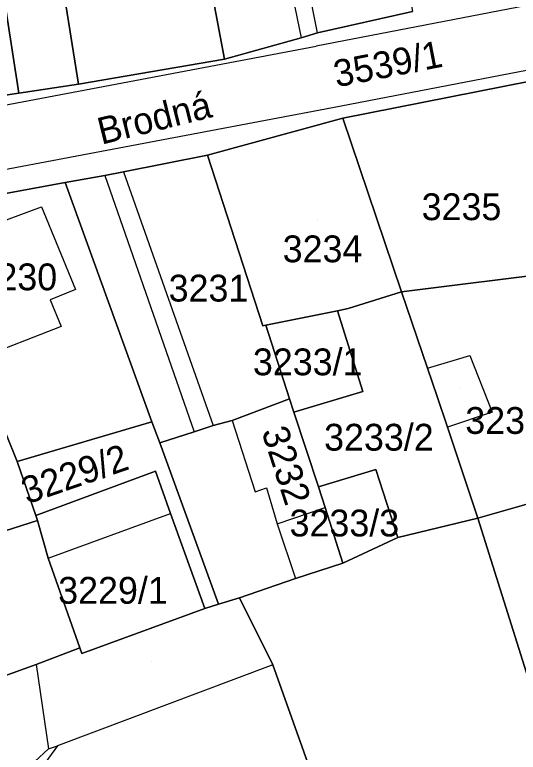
# Model space of a CAD drawing. Extents: x -262657 to -261595, y -1238015 to -1237156.
# Drawn here: x -261893.4 to -261855.8, y -1237748.7 to -1237693.7 of the extents above; entities that cross this region are included whole.
import ezdxf

# ---------------------------------------------------------------- set-up
doc = ezdxf.new("R2010")
doc.units = 0
for name, color, linetype in [('body_kn', 7, 'Continuous'), ('kladpar_druhypozemkov', 7, 'Continuous'), ('kladpar_hranice', 7, 'Continuous'), ('kladpar_parcelnecisla', 7, 'Continuous'), ('kladpar_plochy', 7, 'Continuous'), ('popisy', 7, 'Continuous'), ('zappar_hrandruhpozemk', 7, 'Continuous')]:
    doc.layers.add(name, color=color, linetype=linetype)

msp = doc.modelspace()

# ---------------------------------------------------------------- linework, layer by layer
at = {"layer": 'body_kn'}
for p, q in [((-261872.02, -1237695.41), (-261872.02, -1237695.41)), ((-261870.79, -1237695.02), (-261870.79, -1237695.02)), ((-261870.79, -1237695.02), (-261870.79, -1237695.02)), ((-261870.9, -1237696.02), (-261870.9, -1237696.02)), ((-261877.74, -1237697), (-261877.74, -1237697)), ((-261877.74, -1237697), (-261877.74, -1237697)), ((-261888.62, -1237698.85), (-261888.62, -1237698.85)), ((-261888.62, -1237698.85), (-261888.62, -1237698.85)), ((-261893.08, -1237699.52), (-261893.08, -1237699.52)), ((-261869.66, -1237700.6), (-261869.66, -1237700.6)), ((-261869.66, -1237700.6), (-261869.66, -1237700.6)), ((-261868.9, -1237701.4), (-261868.9, -1237701.4)), ((-261868.9, -1237701.4), (-261868.9, -1237701.4)), ((-261879, -1237704.16), (-261879, -1237704.16)), ((-261879, -1237704.16), (-261879, -1237704.16)), ((-261885.26, -1237705.39), (-261885.26, -1237705.39)), ((-261885.26, -1237705.39), (-261885.26, -1237705.39)), ((-261886.66, -1237705.67), (-261886.66, -1237705.67)), ((-261886.66, -1237705.67), (-261886.66, -1237705.67)), ((-261889.62, -1237706.2), (-261889.62, -1237706.2)), ((-261889.62, -1237706.2), (-261889.62, -1237706.2)), ((-261891.39, -1237708.01), (-261891.39, -1237708.01)), ((-261888.86, -1237714.17), (-261888.86, -1237714.17)), ((-261864.53, -1237714.35), (-261864.53, -1237714.35)), ((-261864.53, -1237714.35), (-261864.53, -1237714.35)), ((-261890.75, -1237714.95), (-261890.75, -1237714.95)), ((-261869.3, -1237715.76), (-261869.3, -1237715.76)), ((-261869.3, -1237715.76), (-261869.3, -1237715.76)), ((-261868.51, -1237715.6), (-261868.51, -1237715.6)), ((-261889.93, -1237716.93), (-261889.93, -1237716.93)), ((-261874.88, -1237716.87), (-261874.88, -1237716.87)), ((-261874.65, -1237716.83), (-261874.65, -1237716.83)), ((-261859.43, -1237719.09), (-261859.43, -1237719.09)), ((-261862.57, -1237720.05), (-261862.57, -1237720.05)), ((-261862.57, -1237720.05), (-261862.57, -1237720.05)), ((-261867.41, -1237721.79), (-261867.41, -1237721.79)), ((-261872.88, -1237722.33), (-261872.88, -1237722.33)), ((-261861.86, -1237722.15), (-261861.86, -1237722.15)), ((-261872.55, -1237723.33), (-261872.55, -1237723.33)), ((-261857.76, -1237723.31), (-261857.76, -1237723.31)), ((-261883.15, -1237724.04), (-261883.15, -1237724.04)), ((-261877.16, -1237723.93), (-261877.16, -1237723.93)), ((-261877.16, -1237723.93), (-261877.16, -1237723.93)), ((-261878.57, -1237724.31), (-261878.57, -1237724.31)), ((-261861.09, -1237724.45), (-261861.09, -1237724.45)), ((-261880, -1237724.78), (-261880, -1237724.78)), ((-261882.57, -1237725.61), (-261882.57, -1237725.61)), ((-261882.57, -1237725.61), (-261882.57, -1237725.61)), ((-261893.22, -1237726.99), (-261893.22, -1237726.99)), ((-261893.22, -1237726.99), (-261893.22, -1237726.99)), ((-261882.89, -1237727.73), (-261882.89, -1237727.73)), ((-261866.43, -1237727.59), (-261866.43, -1237727.59)), ((-261866.43, -1237727.59), (-261866.43, -1237727.59)), ((-261874.6, -1237728.96), (-261874.6, -1237728.96)), ((-261870.72, -1237728.89), (-261870.72, -1237728.89)), ((-261875.45, -1237729.25), (-261875.45, -1237729.25)), ((-261870.21, -1237730.44), (-261870.21, -1237730.44)), ((-261891.81, -1237731.03), (-261891.81, -1237731.03)), ((-261881.77, -1237730.88), (-261881.77, -1237730.88)), ((-261858.82, -1237731.22), (-261858.82, -1237731.22)), ((-261858.82, -1237731.22), (-261858.82, -1237731.22)), ((-261891.68, -1237731.41), (-261891.68, -1237731.41)), ((-261891.68, -1237731.41), (-261891.68, -1237731.41)), ((-261873.79, -1237731.64), (-261873.79, -1237731.64)), ((-261864.8, -1237732.66), (-261864.8, -1237732.66)), ((-261890.9, -1237734.21), (-261890.9, -1237734.21)), ((-261890.9, -1237734.21), (-261890.9, -1237734.21)), ((-261868.9, -1237734.59), (-261868.9, -1237734.59)), ((-261872.44, -1237735.73), (-261872.44, -1237735.73)), ((-261876.61, -1237737.16), (-261876.61, -1237737.16)), ((-261878.19, -1237737.65), (-261878.19, -1237737.65)), ((-261879.2, -1237737.96), (-261879.2, -1237737.96)), ((-261888.53, -1237740.9), (-261888.53, -1237740.9)), ((-261888.53, -1237740.9), (-261888.53, -1237740.9)), ((-261888.38, -1237741.32), (-261888.38, -1237741.32)), ((-261891.79, -1237742.14), (-261891.79, -1237742.14)), ((-261891.79, -1237742.14), (-261891.79, -1237742.14)), ((-261874.12, -1237742.17), (-261874.12, -1237742.17)), ((-261874.12, -1237742.17), (-261874.12, -1237742.17)), ((-261890.21, -1237748.21), (-261890.21, -1237748.21)), ((-261890.88, -1237748.42), (-261890.88, -1237748.42))]:
    msp.add_line(p, q, dxfattribs=at)
at = {"layer": 'kladpar_druhypozemkov'}
for p, q in [((-261865.14, -1237696.86), (-261865.14, -1237696.86)), ((-261859.49, -1237706.97), (-261859.49, -1237706.97)), ((-261870.82, -1237709.03), (-261870.82, -1237709.03)), ((-261879.58, -1237712.98), (-261879.58, -1237712.98)), ((-261871.18, -1237718.51), (-261871.18, -1237718.51)), ((-261860.21, -1237721.57), (-261860.21, -1237721.57)), ((-261865.05, -1237724.07), (-261865.05, -1237724.07)), ((-261887.65, -1237727.31), (-261887.65, -1237727.31)), ((-261872.38, -1237727.33), (-261872.38, -1237727.33)), ((-261867.69, -1237730.79), (-261867.69, -1237730.79)), ((-261885.56, -1237735.83), (-261885.56, -1237735.83)), ((-261883.15, -1237741.94), (-261883.15, -1237741.94))]:
    msp.add_line(p, q, dxfattribs=at)
at = {"layer": 'kladpar_hranice'}
for points in [[(-261888.62, -1237698.85), (-261893.08, -1237699.52), (-261894.9, -1237687.92), (-261895.29, -1237685.45), (-261896.29, -1237679.1), (-261888.4, -1237677.17), (-261881.43, -1237675.43), (-261880.83, -1237679.94), (-261880.07, -1237684.56), (-261890.62, -1237686.47), (-261890.23, -1237688.87), (-261888.62, -1237698.85)], [(-261904.39, -1237680.71), (-261900.65, -1237679.95), (-261896.29, -1237679.1), (-261895.29, -1237685.45), (-261894.9, -1237687.92), (-261893.08, -1237699.52), (-261899.25, -1237700.43), (-261900.74, -1237700.72), (-261902.42, -1237690.86), (-261903.46, -1237685.13), (-261904.39, -1237680.71)], [(-261877.74, -1237697), (-261880.07, -1237684.56), (-261874.6, -1237683.14), (-261874.06, -1237685.43), (-261872.78, -1237685.14), (-261865.48, -1237683.57), (-261863.71, -1237693.45), (-261870.79, -1237695.02), (-261872.02, -1237695.41), (-261877.74, -1237697)], [(-261877.74, -1237697), (-261888.62, -1237698.85), (-261890.23, -1237688.87), (-261890.62, -1237686.47), (-261880.07, -1237684.56), (-261877.74, -1237697)], [(-261815.65, -1237691.39), (-261826.22, -1237693.91), (-261829.24, -1237694.55), (-261838.83, -1237696.08), (-261842.59, -1237696.75), (-261854.92, -1237698.64), (-261868.9, -1237701.4), (-261879, -1237704.16), (-261885.26, -1237705.39), (-261886.66, -1237705.67), (-261889.62, -1237706.2), (-261900.57, -1237708.21)], [(-261899.25, -1237700.43), (-261893.08, -1237699.52), (-261888.62, -1237698.85), (-261877.74, -1237697), (-261872.02, -1237695.41), (-261870.79, -1237695.02), (-261863.71, -1237693.45)], [(-261868.9, -1237701.4), (-261854.92, -1237698.64), (-261853.32, -1237708.24), (-261852.56, -1237712.85), (-261864.53, -1237714.35), (-261868.9, -1237701.4)], [(-261879, -1237704.16), (-261868.9, -1237701.4), (-261864.53, -1237714.35), (-261868.51, -1237715.6), (-261869.3, -1237715.76), (-261874.65, -1237716.83), (-261874.88, -1237716.87), (-261879, -1237704.16)], [(-261889.62, -1237706.2), (-261886.66, -1237705.67), (-261885.26, -1237705.39), (-261879, -1237704.16), (-261874.88, -1237716.87), (-261874.65, -1237716.83), (-261872.88, -1237722.33), (-261877.16, -1237723.93), (-261878.57, -1237724.31), (-261880, -1237724.78), (-261882.57, -1237725.61), (-261883.15, -1237724.04), (-261889.62, -1237706.2)], [(-261900.57, -1237708.21), (-261889.62, -1237706.2), (-261883.15, -1237724.04), (-261893.22, -1237726.99), (-261894.88, -1237722.93), (-261896.2, -1237719.38), (-261897.68, -1237715.63), (-261899.41, -1237710.94), (-261900.57, -1237708.21)], [(-261858.82, -1237731.22), (-261861.09, -1237724.45), (-261861.86, -1237722.15), (-261862.57, -1237720.05), (-261864.53, -1237714.35), (-261852.56, -1237712.85), (-261849.93, -1237728.69), (-261858.82, -1237731.22)], [(-261864.53, -1237714.35), (-261862.57, -1237720.05), (-261861.86, -1237722.15), (-261861.09, -1237724.45), (-261858.82, -1237731.22), (-261864.8, -1237732.66), (-261866.43, -1237727.59), (-261870.72, -1237728.89), (-261872.55, -1237723.33), (-261867.41, -1237721.79), (-261869.3, -1237715.76), (-261868.51, -1237715.6), (-261864.53, -1237714.35)], [(-261869.3, -1237715.76), (-261867.41, -1237721.79), (-261872.55, -1237723.33), (-261872.88, -1237722.33), (-261874.65, -1237716.83), (-261869.3, -1237715.76)], [(-261882.57, -1237725.61), (-261880, -1237724.78), (-261878.57, -1237724.31), (-261877.16, -1237723.93), (-261872.88, -1237722.33), (-261872.55, -1237723.33), (-261870.72, -1237728.89), (-261870.21, -1237730.44), (-261868.9, -1237734.59), (-261872.44, -1237735.73), (-261876.61, -1237737.16), (-261878.19, -1237737.65), (-261882.57, -1237725.61)], [(-261894.88, -1237722.93), (-261893.22, -1237726.99), (-261891.81, -1237731.03), (-261891.68, -1237731.41), (-261905.58, -1237735.82), (-261907.23, -1237726.48), (-261894.88, -1237722.93)], [(-261893.22, -1237726.99), (-261883.15, -1237724.04), (-261882.57, -1237725.61), (-261878.19, -1237737.65), (-261879.2, -1237737.96), (-261881.77, -1237730.88), (-261882.89, -1237727.73), (-261891.81, -1237731.03), (-261893.22, -1237726.99)], [(-261891.68, -1237731.41), (-261891.81, -1237731.03), (-261882.89, -1237727.73), (-261881.77, -1237730.88), (-261879.2, -1237737.96), (-261888.38, -1237741.32), (-261888.53, -1237740.9), (-261890.9, -1237734.21), (-261891.68, -1237731.41)], [(-261866.43, -1237727.59), (-261864.8, -1237732.66), (-261868.9, -1237734.59), (-261870.21, -1237730.44), (-261870.72, -1237728.89), (-261866.43, -1237727.59)], [(-261849.93, -1237728.69), (-261845.54, -1237739.43), (-261834.22, -1237737.38), (-261832.97, -1237741.84), (-261853.4, -1237748.46), (-261858.82, -1237731.22), (-261849.93, -1237728.69)], [(-261811.6, -1237755.76), (-261860.68, -1237774.55), (-261869.5, -1237752.69), (-261870.26, -1237752.98), (-261874.12, -1237742.17), (-261876.61, -1237737.16), (-261872.44, -1237735.73), (-261868.9, -1237734.59), (-261864.8, -1237732.66), (-261858.82, -1237731.22), (-261853.4, -1237748.46), (-261848.36, -1237764.27), (-261828.48, -1237757.63), (-261832.97, -1237741.84), (-261834.22, -1237737.38), (-261830.6, -1237736.72), (-261825.65, -1237735.22), (-261815.77, -1237729.89), (-261810.09, -1237729.46)], [(-261888.53, -1237740.9), (-261891.79, -1237742.14), (-261905.24, -1237747), (-261907.41, -1237736.41), (-261905.58, -1237735.82), (-261891.68, -1237731.41), (-261890.9, -1237734.21), (-261888.53, -1237740.9)], [(-261920.12, -1237752.32), (-261918.2, -1237751.63), (-261905.24, -1237747), (-261891.79, -1237742.14), (-261888.53, -1237740.9), (-261888.38, -1237741.32), (-261879.2, -1237737.96), (-261878.19, -1237737.65), (-261876.61, -1237737.16), (-261874.12, -1237742.17), (-261870.26, -1237752.98), (-261885.56, -1237759.1), (-261886.5, -1237759.27), (-261888.28, -1237759.8), (-261893.1, -1237761.58), (-261893.41, -1237761.04), (-261899.15, -1237763.26), (-261908.04, -1237766.48), (-261913.16, -1237768.28), (-261915.03, -1237763.93), (-261915.64, -1237762.81), (-261920.12, -1237752.32)]]:
    msp.add_lwpolyline(points, dxfattribs=at)
at = {"layer": 'kladpar_plochy'}
for points in [[(-261888.62, -1237698.85), (-261893.08, -1237699.52), (-261894.9, -1237687.92), (-261895.29, -1237685.45), (-261896.29, -1237679.1), (-261888.4, -1237677.17), (-261881.43, -1237675.43), (-261880.83, -1237679.94), (-261880.07, -1237684.56), (-261890.62, -1237686.47), (-261890.23, -1237688.87)], [(-261904.39, -1237680.71), (-261900.65, -1237679.95), (-261896.29, -1237679.1), (-261895.29, -1237685.45), (-261894.9, -1237687.92), (-261893.08, -1237699.52), (-261899.25, -1237700.43), (-261900.74, -1237700.72), (-261902.42, -1237690.86), (-261903.46, -1237685.13)], [(-261877.74, -1237697), (-261880.07, -1237684.56), (-261874.6, -1237683.14), (-261874.06, -1237685.43), (-261872.78, -1237685.14), (-261865.48, -1237683.57), (-261863.71, -1237693.45), (-261870.79, -1237695.02), (-261872.02, -1237695.41)], [(-261877.74, -1237697), (-261888.62, -1237698.85), (-261890.23, -1237688.87), (-261890.62, -1237686.47), (-261880.07, -1237684.56)], [(-261868.9, -1237701.4), (-261854.92, -1237698.64), (-261853.32, -1237708.24), (-261852.56, -1237712.85), (-261864.53, -1237714.35)], [(-261879, -1237704.16), (-261868.9, -1237701.4), (-261864.53, -1237714.35), (-261868.51, -1237715.6), (-261869.3, -1237715.76), (-261874.65, -1237716.83), (-261874.88, -1237716.87)], [(-261889.62, -1237706.2), (-261886.66, -1237705.67), (-261885.26, -1237705.39), (-261879, -1237704.16), (-261874.88, -1237716.87), (-261874.65, -1237716.83), (-261872.88, -1237722.33), (-261877.16, -1237723.93), (-261878.57, -1237724.31), (-261880, -1237724.78), (-261882.57, -1237725.61), (-261883.15, -1237724.04)], [(-261900.57, -1237708.21), (-261889.62, -1237706.2), (-261883.15, -1237724.04), (-261893.22, -1237726.99), (-261894.88, -1237722.93), (-261896.2, -1237719.38), (-261897.68, -1237715.63), (-261899.41, -1237710.94)], [(-261858.82, -1237731.22), (-261861.09, -1237724.45), (-261861.86, -1237722.15), (-261862.57, -1237720.05), (-261864.53, -1237714.35), (-261852.56, -1237712.85), (-261849.93, -1237728.69)], [(-261864.53, -1237714.35), (-261862.57, -1237720.05), (-261861.86, -1237722.15), (-261861.09, -1237724.45), (-261858.82, -1237731.22), (-261864.8, -1237732.66), (-261866.43, -1237727.59), (-261870.72, -1237728.89), (-261872.55, -1237723.33), (-261867.41, -1237721.79), (-261869.3, -1237715.76), (-261868.51, -1237715.6)], [(-261869.3, -1237715.76), (-261867.41, -1237721.79), (-261872.55, -1237723.33), (-261872.88, -1237722.33), (-261874.65, -1237716.83)], [(-261882.57, -1237725.61), (-261880, -1237724.78), (-261878.57, -1237724.31), (-261877.16, -1237723.93), (-261872.88, -1237722.33), (-261872.55, -1237723.33), (-261870.72, -1237728.89), (-261870.21, -1237730.44), (-261868.9, -1237734.59), (-261872.44, -1237735.73), (-261876.61, -1237737.16), (-261878.19, -1237737.65)], [(-261894.88, -1237722.93), (-261893.22, -1237726.99), (-261891.81, -1237731.03), (-261891.68, -1237731.41), (-261905.58, -1237735.82), (-261907.23, -1237726.48)], [(-261893.22, -1237726.99), (-261883.15, -1237724.04), (-261882.57, -1237725.61), (-261878.19, -1237737.65), (-261879.2, -1237737.96), (-261881.77, -1237730.88), (-261882.89, -1237727.73), (-261891.81, -1237731.03)], [(-261891.68, -1237731.41), (-261891.81, -1237731.03), (-261882.89, -1237727.73), (-261881.77, -1237730.88), (-261879.2, -1237737.96), (-261888.38, -1237741.32), (-261888.53, -1237740.9), (-261890.9, -1237734.21)], [(-261866.43, -1237727.59), (-261864.8, -1237732.66), (-261868.9, -1237734.59), (-261870.21, -1237730.44), (-261870.72, -1237728.89)], [(-261849.93, -1237728.69), (-261845.54, -1237739.43), (-261834.22, -1237737.38), (-261832.97, -1237741.84), (-261853.4, -1237748.46), (-261858.82, -1237731.22)], [(-261810.09, -1237729.46), (-261811.6, -1237755.76), (-261860.68, -1237774.55), (-261869.5, -1237752.69), (-261870.26, -1237752.98), (-261874.12, -1237742.17), (-261876.61, -1237737.16), (-261872.44, -1237735.73), (-261868.9, -1237734.59), (-261864.8, -1237732.66), (-261858.82, -1237731.22), (-261853.4, -1237748.46), (-261848.36, -1237764.27), (-261828.48, -1237757.63), (-261832.97, -1237741.84), (-261834.22, -1237737.38), (-261830.6, -1237736.72), (-261825.65, -1237735.22), (-261815.77, -1237729.89)], [(-261888.53, -1237740.9), (-261891.79, -1237742.14), (-261905.24, -1237747), (-261907.41, -1237736.41), (-261905.58, -1237735.82), (-261891.68, -1237731.41), (-261890.9, -1237734.21)], [(-261920.12, -1237752.32), (-261918.2, -1237751.63), (-261905.24, -1237747), (-261891.79, -1237742.14), (-261888.53, -1237740.9), (-261888.38, -1237741.32), (-261879.2, -1237737.96), (-261878.19, -1237737.65), (-261876.61, -1237737.16), (-261874.12, -1237742.17), (-261870.26, -1237752.98), (-261885.56, -1237759.1), (-261886.5, -1237759.27), (-261888.28, -1237759.8), (-261893.1, -1237761.58), (-261893.41, -1237761.04), (-261899.15, -1237763.26), (-261908.04, -1237766.48), (-261913.16, -1237768.28), (-261915.03, -1237763.93), (-261915.64, -1237762.81)]]:
    msp.add_lwpolyline(points, close=True, dxfattribs=at)
for points in [[(-261815.65, -1237691.39), (-261826.22, -1237693.91), (-261829.24, -1237694.55), (-261838.83, -1237696.08), (-261842.59, -1237696.75), (-261854.92, -1237698.64), (-261868.9, -1237701.4), (-261879, -1237704.16), (-261885.26, -1237705.39), (-261886.66, -1237705.67), (-261889.62, -1237706.2), (-261900.57, -1237708.21)], [(-261899.25, -1237700.43), (-261893.08, -1237699.52), (-261888.62, -1237698.85), (-261877.74, -1237697), (-261872.02, -1237695.41), (-261870.79, -1237695.02), (-261863.71, -1237693.45)]]:
    msp.add_lwpolyline(points, dxfattribs=at)
at = {"layer": 'zappar_hrandruhpozemk'}
for p, q in [((-261874.06, -1237685.43), (-261872.02, -1237695.41)), ((-261870.79, -1237695.02), (-261872.78, -1237685.14)), ((-261831.35, -1237688.4), (-261870.9, -1237696.02)), ((-261934.58, -1237708.05), (-261870.9, -1237696.02)), ((-261932.89, -1237712.5), (-261869.66, -1237700.6)), ((-261885.26, -1237705.39), (-261878.57, -1237724.31)), ((-261886.66, -1237705.67), (-261880, -1237724.78)), ((-261899.41, -1237710.94), (-261891.39, -1237708.01)), ((-261891.39, -1237708.01), (-261888.86, -1237714.17)), ((-261862.57, -1237720.05), (-261859.43, -1237719.09)), ((-261859.43, -1237719.09), (-261857.76, -1237723.31)), ((-261857.76, -1237723.31), (-261861.09, -1237724.45)), ((-261874.6, -1237728.96), (-261873.79, -1237731.64)), ((-261873.79, -1237731.64), (-261870.21, -1237730.44)), ((-261890.9, -1237734.21), (-261881.77, -1237730.88)), ((-261873.79, -1237731.64), (-261872.44, -1237735.73)), ((-261891.79, -1237742.14), (-261890.88, -1237748.42)), ((-261874.12, -1237742.17), (-261890.21, -1237748.21))]:
    msp.add_line(p, q, dxfattribs=at)
for points in [[(-261869.66, -1237700.6), (-261840.58, -1237695.01), (-261829.72, -1237692.94), (-261829.24, -1237694.55)], [(-261888.86, -1237714.17), (-261890.75, -1237714.95), (-261889.93, -1237716.93), (-261896.2, -1237719.38)], [(-261877.16, -1237723.93), (-261875.45, -1237729.25), (-261874.6, -1237728.96)], [(-261891.88, -1237749.38), (-261890.88, -1237748.42), (-261890.21, -1237748.21), (-261891.54, -1237750.05), (-261902.16, -1237755.36), (-261902.66, -1237756.91)]]:
    msp.add_lwpolyline(points, dxfattribs=at)

# ---------------------------------------------------------------- texts
at = {"layer": 'kladpar_parcelnecisla'}
for s, rotation, p in [('3539/1', 11, (-261869.373, -1237699.099)), ('3232', 288, (-261874.989, -1237724.752)), ('3229/2', 19, (-261892.463, -1237730.202))]:
    msp.add_text(s, height=2, rotation=rotation, dxfattribs=at).set_placement(p)
for s, p in [('3235', (-261863.017, -1237709)), ('3234', (-261873.391, -1237712.14)), ('3230', (-261896.173, -1237714.23)), ('3231', (-261881.902, -1237715.07)), ('3233/1', (-261875.614, -1237720.57)), ('3236', (-261859.761, -1237724.94)), ('3233/2', (-261870.3, -1237726.19)), ('3233/3', (-261872.876, -1237732.59)), ('3229/1', (-261890.146, -1237737.61))]:
    msp.add_text(s, height=2, dxfattribs=at).set_placement(p)
at = {"layer": 'popisy'}
msp.add_text('Brodná', height=2, rotation=14, dxfattribs=at).set_placement((-261886.918, -1237703.38))

doc.saveas('drawing.dxf')
